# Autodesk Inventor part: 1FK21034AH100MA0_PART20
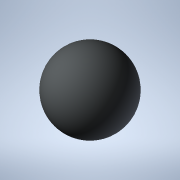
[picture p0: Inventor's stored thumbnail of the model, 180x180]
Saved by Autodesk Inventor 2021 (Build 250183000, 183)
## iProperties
Created: 2025-04
Part Number: 1FK21034AH100MA0_PART20
Material: Generic
Catalog Web Link: www.3dfindit.com
Description: -Servo synchronous motor
Document SubType Name: Modeling
Designer: psAdmin
Mass: 0.113097 g
Surface Area: 1.13097 cm^2
Volume: 0.113097 cm^3
Density: 1 g/cm^3
Appearance: PSOLRGB-212-217-219
Category: PARTsolutions
Title: 1FK21034AH100MA0_PART20
Author: Cadenas PARTsolutions
Comments: Servo synchronous motor
Sending System: PARTsolutions
Preprocessor: ST-DEVELOPER v19.3
PSOL_IDENT_0: {$CADENAS_DATA/23d-libs/siemens_ag/_cat_/39/97/1fk21034ah100ma0.prj},216 {VTYP=3D},{NB=1FK21034AH100
PSOL_IDENT_1: MA0_PART20},{LINA=1FK21034AH100MA0_PART20},{NN=1FK21034AH100MA0_PART20},{NOPRJ=TRUE},{DATE=19.08.202
PSOL_IDENT_2: 5 14:00:33},{GEOMDATE=30.07.2025 02:02:21},{VERSION=},{LINEID=10},{WBVAR=},{WBNUMERIC=}  {NB=1FK2103
PSOL_IDENT_3: 4AH100MA0_PART20},{LINA=1FK21034AH100MA0_PART20},{KT=DUMMY},{PREVIEW=../../../_pool_/d3/78/p_d211_xx
PSOL_IDENT_4: _00934j.png},{DESCSHORT=SIMOTICS S-1FK2 HD, SINAMICS S210 3AC 400V-480V, 1.01 Nm, 4500 rpm},{DESCLON
PSOL_IDENT_5: G=SIMOTICS S-1FK2 HD servo motor M0=1.27 Nm; PN = 0.48 kW at nN=4500 rpm (380-480 V); PN = 0.3 kW at
PSOL_IDENT_6: nN=2500 rpm (200-240 V); with holding brake; degree of protection IP64; cylindrical shaft D14 x 30
PSOL_IDENT_7: mm; absolute encoder 22-bit + 12-bit multiturn (encoder AM22DQC); with OCC interface; plug size M17,
PSOL_IDENT_8: rotatable; SIMOTICS S-1FK2 servomotorfor a wide range of uses in industrial environments. SIMOTICS
PSOL_IDENT_9: S‑1FK2 servomotors are compact synchronous motors with a high dynamic performance that set themselve
PSOL_IDENT_10: s apart as a result of their high power density, degree of protection and overload capability. The m
PSOL_IDENT_11: otors are available in two variants: as High Dynamic variant (highest dynamic performance as a resul
PSOL_IDENT_12: t of the low intrinsic moment of inertia for applications demanding a high dynamic performance with
PSOL_IDENT_13: low moved masses) - and as Compact variant (precise and stable closed-loop control for medium up to
PSOL_IDENT_14: large moved masses as a result of a medium intrinsic moment of inertia). SIMOTICSS‑1FK2 servomotors
PSOL_IDENT_15: fully exploit their strengths in a system with the SINAMICSS210 frequency converter and simple conne
PSOL_IDENT_16: ction using the one cable connection (OCC). Advantages include the short control and positioning tim
PSOL_IDENT_17: es, fast and precise correction of disturbing quantities as well as stable control with a high dynam
PSOL_IDENT_18: ic performance. The servo motors can be configured to address a wide range of requirements. For exam
PSOL_IDENT_19: ple with and without holding brake, IP64 or IP65 degree of protection, singleturn or multiturn absol
PSOL_IDENT_20: ute encoders - to name just a few. Further, the servomotors are available in different shaft heights
PSOL_IDENT_21: extending from 20 to 100. A shaft sealing ring is available to achieve an IP65 degree of protection
PSOL_IDENT_22: and for subsequent mounting at the motor or as spare part. SIMOTICS - the optimum motor for each an
PSOL_IDENT_23: d every motion control application.},{INTNO=195125454019},{SUPPLIERALTNO=1FK2103-4AH10-0MA0},{MANUID=
PSOL_IDENT_24: 1FK21034AH100MA0},{MANUNAME=Siemens},{MANUTYPEDESC=SYNCHRONOUS MOTOR 1FK2 HD 1,27 NM},{AAU732=SIMOTI
PSOL_IDENT_25: CS},{AAO057=S-1FK2},{AAU734=SIMOTICS S-1FK2 HD servo motor M0=1.27 Nm; PN = 0.48 kW at nN=4500 rpm (
PSOL_IDENT_26: 380-480 V); PN = 0.3 kW at nN=2500 rpm (200-240 V); with holding brake; degree of protection IP64; c
PSOL_IDENT_27: ylindrical shaft D14 x 30 mm; absolute encoder 22-bit + 12-bit multiturn (encoder AM22DQC); with OCC
PSOL_IDENT_28: interface; plug size M17, rotatable;},{AAW338=SYNCHRONOUS MOTOR 1FK2 HD 1,27 NM},{AAO742=SIMOTICS},
PSOL_IDENT_29: {AAO663=4034106444921},{NOCUPEROU=1},{PRICEQUANTITY=1},{QUANTITYMIN=1},{QUANTITYINT=1},{CTN=85015100
PSOL_IDENT_30: },{COO=RO},{AAO676=1FK2103-4AH10-0MA0},{AAO677=Siemens AG},{ORDERUNIT=C62},{CONTENTUNIT=C62}
NB: 1FK21034AH100MA0_PART20
NT: Servo synchronous motor
NBSYN: $MANUID._PART20
LINA: 1FK21034AH100MA0_PART20
CATALOG: SIEMENS
PREVIEW: ../../../_pool_/d3/78/p_d211_xx_00934j.png
DESCSHORT: SIMOTICS S-1FK2 HD, SINAMICS S210 3AC 400V-480V, 1.01 Nm, 4500 rpm
DESCLONG: SIMOTICS S-1FK2 HD servo motor M0=1.27 Nm; PN = 0.48 kW at nN=4500 rpm (380-480 V); PN = 0.3 kW at nN=2500 rpm (200-240 V); with holding brake; degree of protec
INTNO: 195125454019
SUPPLIERALTNO: 1FK2103-4AH10-0MA0
MANUID: 1FK21034AH100MA0
MANUNAME: Siemens
MANUTYPEDESC: SYNCHRONOUS MOTOR 1FK2 HD 1,27 NM
AAU732: SIMOTICS
AAO057: S-1FK2
AAU734: SIMOTICS S-1FK2 HD servo motor M0=1.27 Nm; PN = 0.48 kW at nN=4500 rpm (380-480 V); PN = 0.3 kW at nN=2500 rpm (200-240 V); with holding brake; degree of protec
AAW338: SYNCHRONOUS MOTOR 1FK2 HD 1,27 NM
AAO742: SIMOTICS
AAO663: 4034106444921.0
NOCUPEROU: 1
PRICEQUANTITY: 1
QUANTITYMIN: 1
QUANTITYINT: 1
CTN: 85015100
COO: RO
ARTICLENO: 1FK21034AH100MA0_PART20
BOMINFO: 1FK21034AH100MA0_PART20
CREATOR: CADENAS GmbH
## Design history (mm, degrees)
feature "2025_04_17_15_09_00_0361"
body "Solid1"
